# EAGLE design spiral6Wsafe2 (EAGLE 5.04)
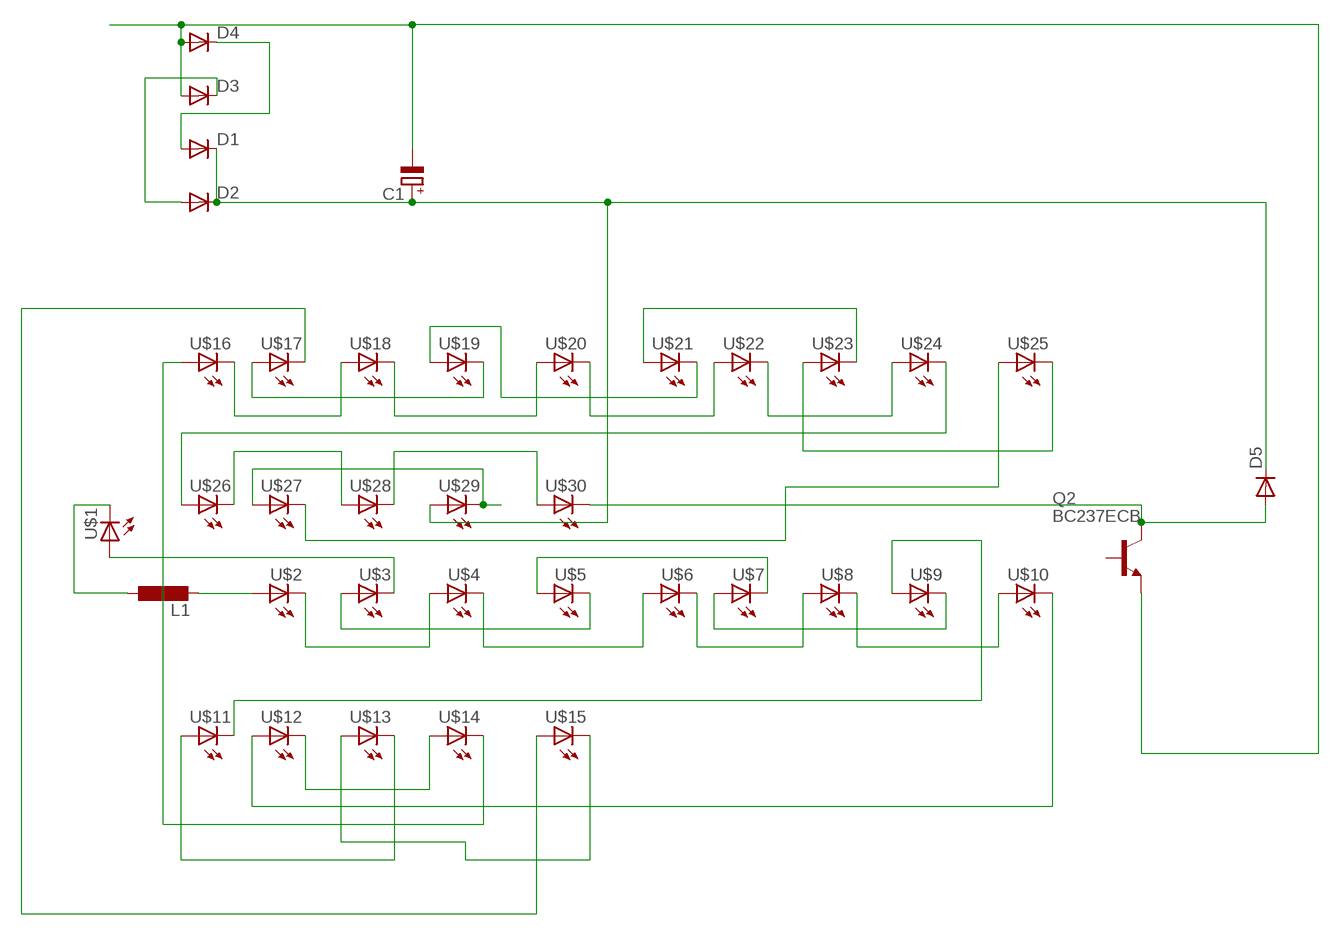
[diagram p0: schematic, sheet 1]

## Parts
C1  CPOL-EUE5-8.5  [E5-8,5]
D1  DIODE-D-5  [D-5]
D2  DIODE-D-5  [D-5]
D3  DIODE-D-5  [D-5]
D4  DIODE-D-5  [D-5]
D5  DIODE-D-2.5  [D-2.5]
L1  L-EU0207/10  [0207/10]
Q2  BC237ECB  [TO92-BCE]
U$1  LED5MM  [LED5MM]
U$2  LED5MM  [LED5MM]
U$3  LED5MM  [LED5MM]
U$4  LED5MM  [LED5MM]
U$5  LED5MM  [LED5MM]
U$6  LED5MM  [LED5MM]
U$7  LED5MM  [LED5MM]
U$8  LED5MM  [LED5MM]
U$9  LED5MM  [LED5MM]
U$10  LED5MM  [LED5MM]
U$11  LED5MM  [LED5MM]
U$12  LED5MM  [LED5MM]
U$13  LED5MM  [LED5MM]
U$14  LED5MM  [LED5MM]
U$15  LED5MM  [LED5MM]
U$16  LED5MM  [LED5MM]
U$17  LED5MM  [LED5MM]
U$18  LED5MM  [LED5MM]
U$19  LED5MM  [LED5MM]
U$20  LED5MM  [LED5MM]
U$21  LED5MM  [LED5MM]
U$22  LED5MM  [LED5MM]
U$23  LED5MM  [LED5MM]
U$24  LED5MM  [LED5MM]
U$25  LED5MM  [LED5MM]
U$26  LED5MM  [LED5MM]
U$27  LED5MM  [LED5MM]
U$28  LED5MM  [LED5MM]
U$29  LED5MM  [LED5MM]
U$30  LED5MM  [LED5MM]

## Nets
N$1: C1.- D3.A D4.A Q2.B(E)
N$2: U$2.K(C) U$4.A
N$3: U$4.K(C) U$6.A
N$4: U$6.K(C) U$8.A
N$5: U$8.K(C) U$10.A
N$6: U$1.A U$3.K(C)
N$7: U$3.A U$5.K(C)
N$8: U$5.A U$7.K(C)
N$9: U$7.A U$9.K(C)
N$10: U$10.K(C) U$12.A
N$11: U$12.K(C) U$14.A
N$12: U$14.K(C) U$16.A
N$13: U$16.K(C) U$18.A
N$14: U$18.K(C) U$20.A
N$15: U$20.K(C) U$22.A
N$16: U$22.K(C) U$24.A
N$17: U$24.K(C) U$26.A
N$18: U$26.K(C) U$28.A
N$19: U$28.K(C) U$30.A
N$20: C1.+ D1.C D2.C D5.C U$29.A
N$21: L1.2 U$2.A
N$22: L1.1 U$1.K(C)
N$23: U$27.A U$29.K(C)
N$24: U$25.A U$27.K(C)
N$25: D1.A D4.C
N$26: D2.A D3.C
N$27: U$9.A U$11.K(C)
N$29: U$11.A U$13.K(C)
N$30: U$13.A U$15.K(C)
N$31: U$15.A U$17.K(C)
N$32: U$17.A U$19.K(C)
N$33: U$19.A U$21.K(C)
N$34: U$21.A U$23.K(C)
N$35: U$23.A U$25.K(C)
N$36: D5.A Q2.C U$30.K(C)
Unconnected: Q2.E(B)

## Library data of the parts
C1 = rcl-2:CPOL-EU: POLARIZED CAPACITOR, European symbol
D1-D5 = diode-1:DIODE-: DIODE
L1 = rcl-2:L-EU: INDUCTOR, European symbol
Q2 = transistor-npn:BC237: NPN Transistor
U$1-U$30 = led(2):LED: LED

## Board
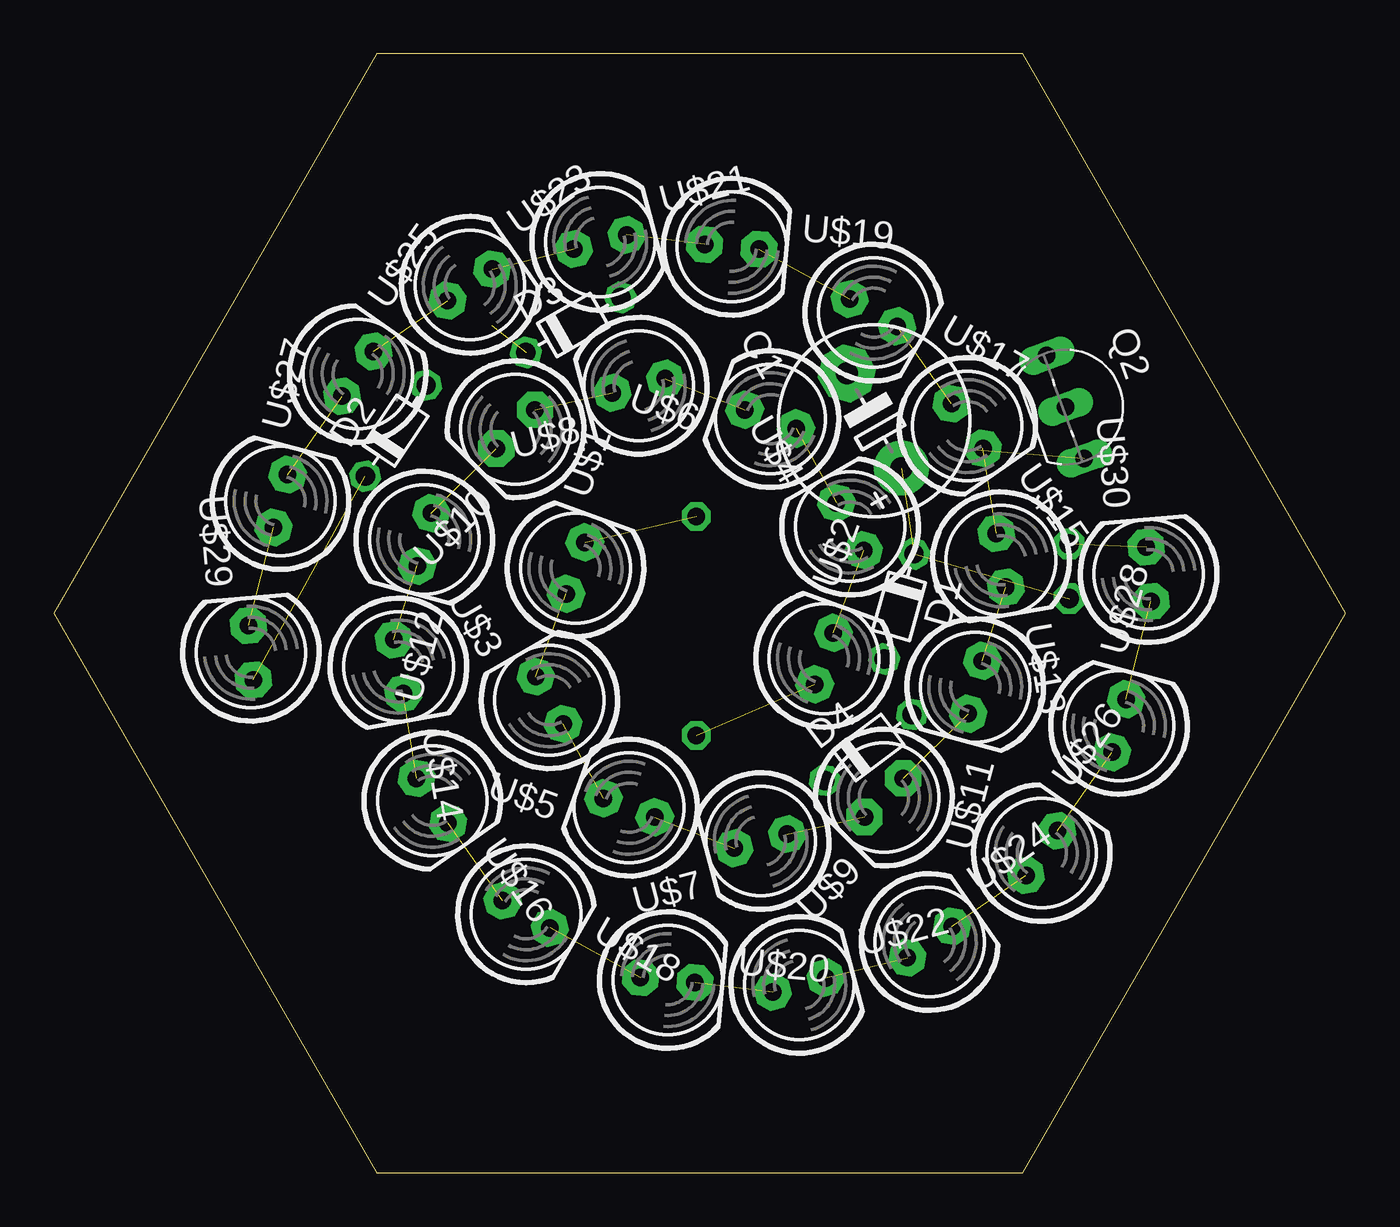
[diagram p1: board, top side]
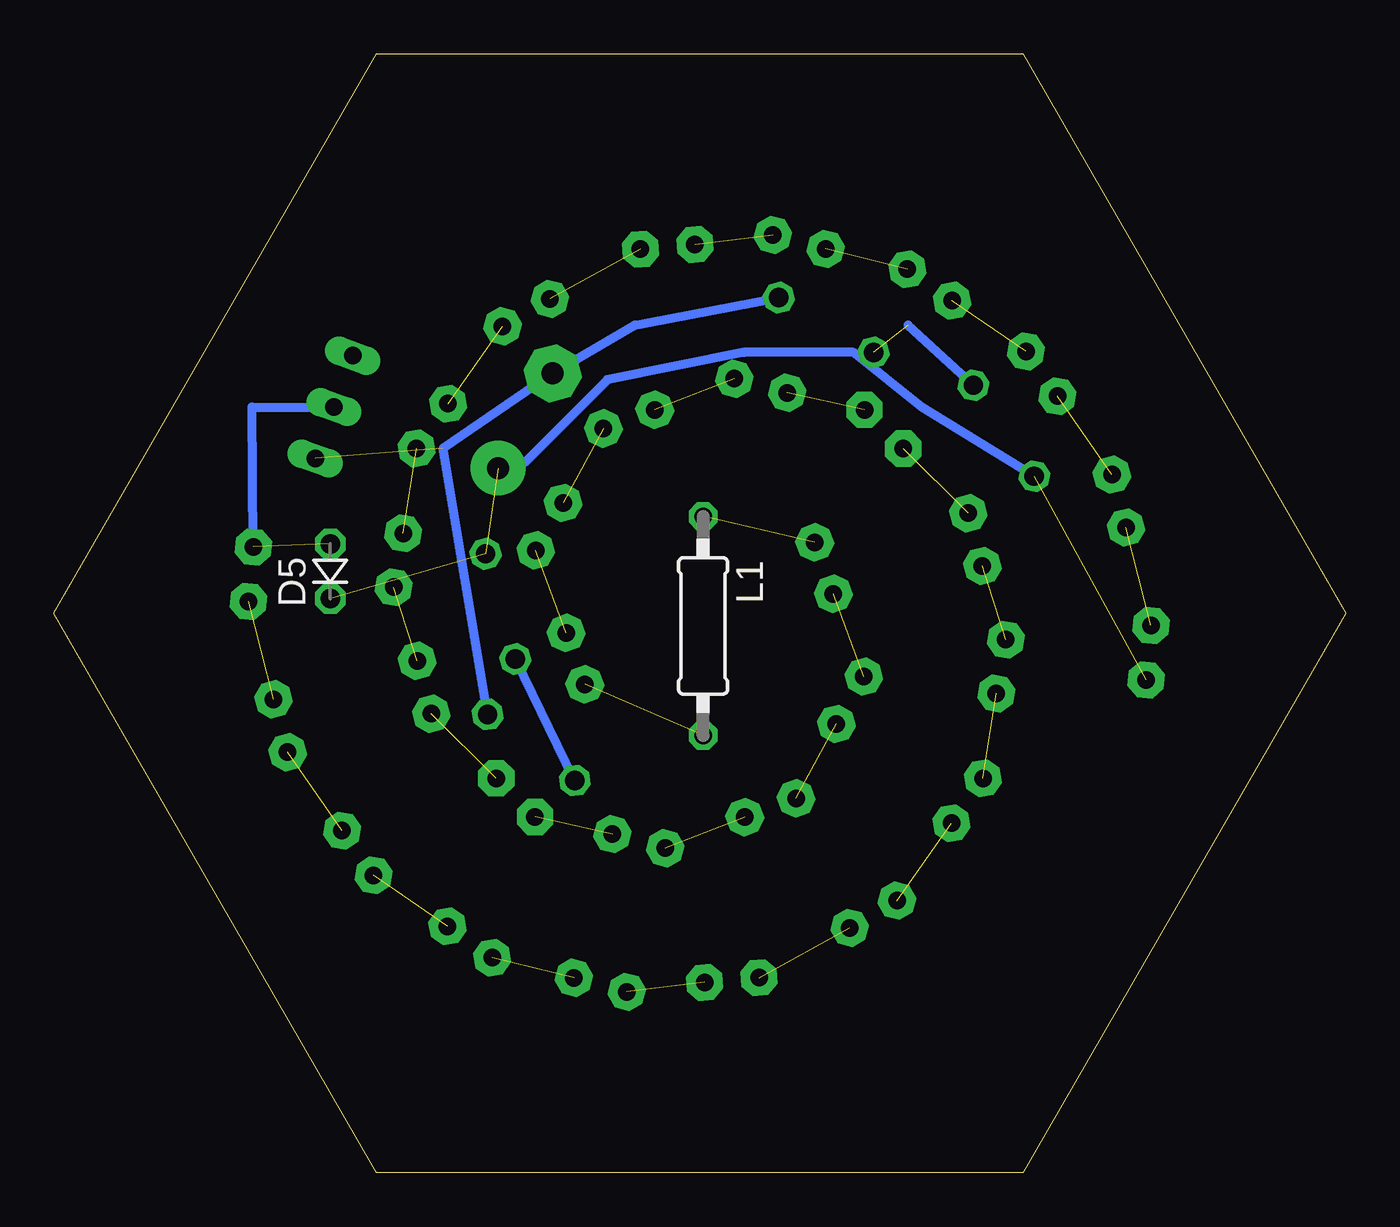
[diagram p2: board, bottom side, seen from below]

Size 60 x 51.96 mm. Coordinates in mm from the lower left corner, seen from the top.
Outline: 15,0 45,0 60,25.98 45,51.96 15,51.96 0,25.98 15,0
Copper layers (1*16): Top 0.035mm / dielectric 1.5mm / Bottom 0.035mm
Design rules "default": minimum track width 10mil, minimum drill 24mil, track to track 8mil, track to pad 8mil, pad to pad 8mil, via to via 8mil, smd to smd 8mil, copper to edge 40mil, drill to drill 8mil, minimum pad ring 10mil, minimum via ring 8mil, stop-mask expansion 4mil, vias tented up to drill 0mil, thermal gap 10mil

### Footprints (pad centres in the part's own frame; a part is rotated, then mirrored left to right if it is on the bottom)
E5-8,5 = drill 1.016 pad 2.54 round: + -2.54,0 | drill 1.016 pad 2.54 octagon: - 2.54,0
D-5 = drill 0.9 octagon: A 2.54,0; C -2.54,0
D-2.5 = drill 0.9 octagon: A 1.27,0; C -1.27,0
0207/10 = drill 0.813 octagon: 1 -5.08,0; 2 5.08,0
TO92-BCE = drill 0.813 long: B 2.54,0; C 0,0; E -2.54,0
LED5MM = drill 0.813 pad 1.676 octagon: A -1.27,0; K 1.27,0

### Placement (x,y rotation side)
C1  38.1,34.92 120 top
D1  39.26,26.31 254.2 top
D2  15.88,34.46 56.2 top
D3  24.13,39.37 30 top
D4  37.83,19.76 37.2 top
D5  47.16,27.94 90 bottom
L1  29.84,25.4 270 bottom
Q2  46.99,35.56 290 top
U$1  24.23,28.08 70 top
U$2  35.77,23.88 70 top
U$3  23.02,21.95 120 top
U$4  36.98,30.01 120 top
U$5  26.72,16.96 160 top
U$6  33.28,35 160 top
U$7  32.83,15.41 195 top
U$8  27.17,36.55 195 top
U$9  38.55,17.43 225 top
U$10  21.45,34.53 225 top
U$11  42.8,22.55 255 top
U$12  17.2,29.41 255 top
U$13  43.99,28.45 280 top
U$14  16.01,23.51 280 top
U$15  42.42,34.68 305 top
U$16  17.58,17.28 305 top
U$17  38.06,39.95 330 top
U$18  21.94,12.01 330 top
U$19  31.49,43 355 top
U$20  28.51,8.96 355 top
U$21  25.38,43.23 14.9 top
U$22  34.62,8.73 14.9 top
U$23  19.32,41.23 35 top
U$24  40.68,10.73 35 top
U$25  14.12,37.1 54.9 top
U$26  45.88,14.86 54.9 top
U$27  10.53,31.2 75 top
U$28  49.47,20.76 75 top
U$29  9.15,24.16 95 top
U$30  50.85,27.8 95 top

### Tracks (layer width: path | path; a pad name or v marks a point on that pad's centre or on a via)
N$1  (1 unrouted)
  Bottom 0.406: D3.A 33.02,39.37 C1.- 41.91,33.66 D4.A
N$2  (1 unrouted)
N$3  (1 unrouted)
N$4  (1 unrouted)
N$5  (1 unrouted)
N$6  (1 unrouted)
N$7  (1 unrouted)
N$8  (1 unrouted)
N$9  (1 unrouted)
N$10  (1 unrouted)
N$11  (1 unrouted)
N$12  (1 unrouted)
N$13  (1 unrouted)
N$14  (1 unrouted)
N$15  (1 unrouted)
N$16  (1 unrouted)
N$17  (1 unrouted)
N$18  (1 unrouted)
N$19  (1 unrouted)
N$20  (3 unrouted)
  Bottom 0.406: D2.C 19.68,35.56 22.86,38.1 27.94,38.1 34.29,36.83 38.1,33.02 C1.+
N$21  (1 unrouted)
N$22  (1 unrouted)
N$23  (1 unrouted)
N$24  (1 unrouted)
N$25
  Bottom 0.406: D4.C D1.A
N$26  (1 unrouted)
  Bottom 0.406: D2.A 20.32,39.37
N$27  (1 unrouted)
N$29  (1 unrouted)
N$30  (1 unrouted)
N$31  (1 unrouted)
N$32  (1 unrouted)
N$33  (1 unrouted)
N$34  (1 unrouted)
N$35  (1 unrouted)
N$36  (1 unrouted)
  Bottom 0.406: Q2.C 50.8,35.56 U$30.K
